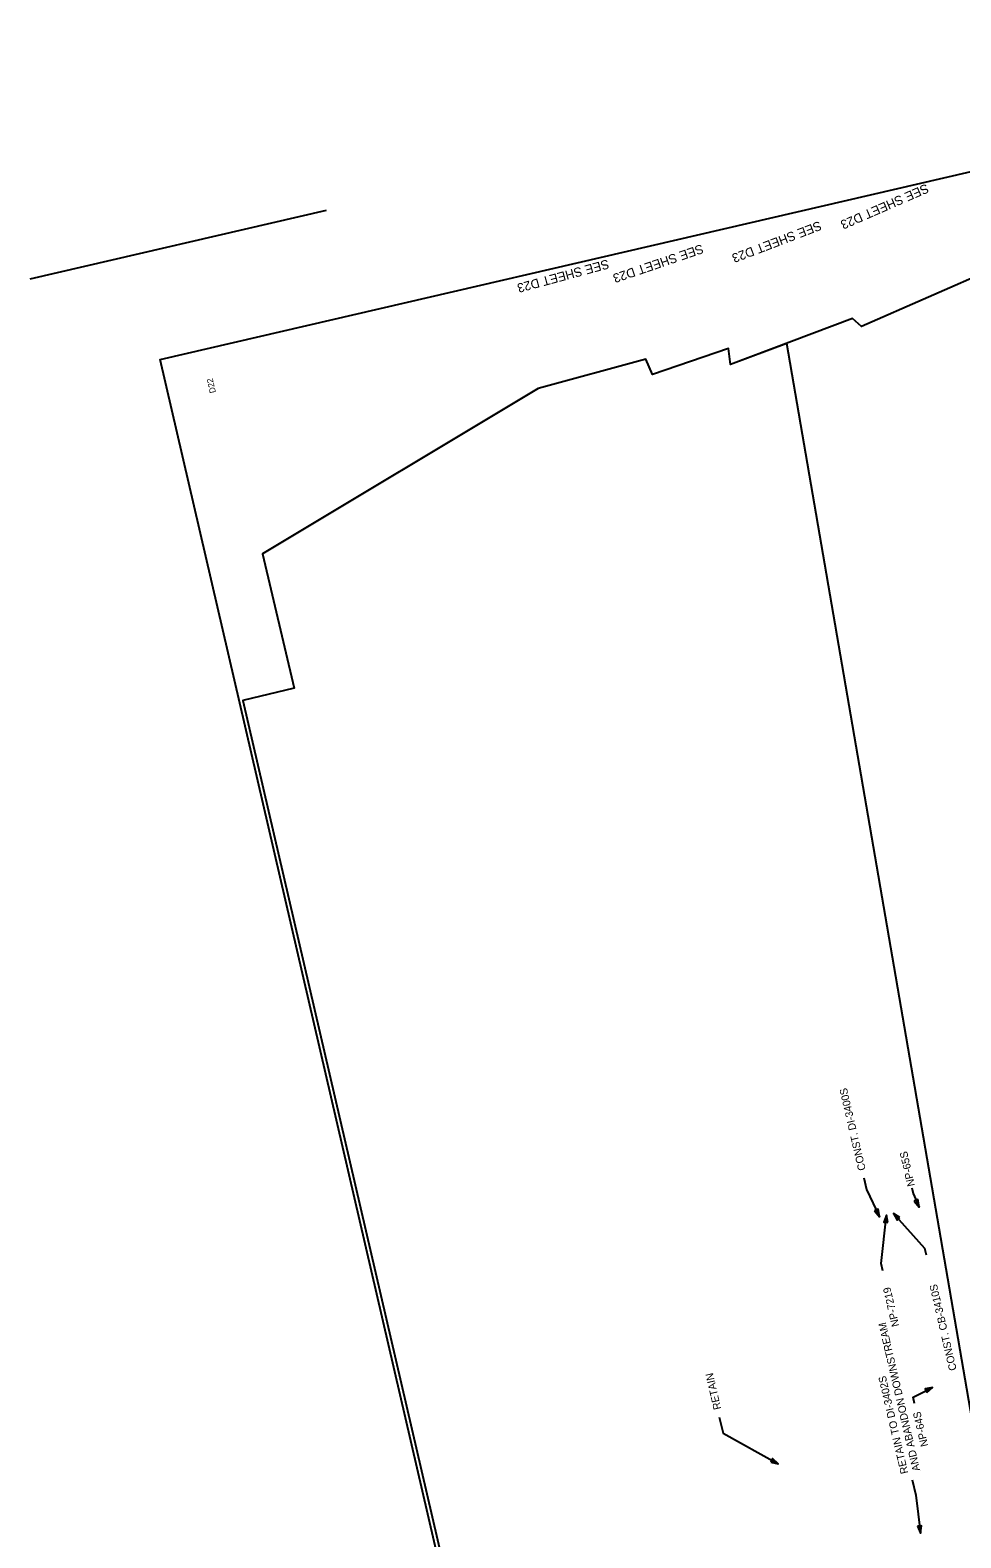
# Model space of a CAD drawing. Extents: x 1611522 to 1613146, y 1089913 to 1091760.
# Drawn here: x 1611522 to 1612133, y 1090772 to 1091760 of the extents above; entities that cross this region are included whole.
import ezdxf

# ---------------------------------------------------------------- set-up
doc = ezdxf.new("R2010")
doc.units = 0
for name, color, linetype in [('Level 2', 7, 'Continuous'), ('Plan_Clip', 7, 'Continuous'), ('RD_SHT_Bndy', 7, 'Continuous'), ('RD_SHT_MatchLine', 7, 'Continuous'), ('RD_TX_Drainage', 7, 'Continuous')]:
    doc.layers.add(name, color=color, linetype=linetype)

msp = doc.modelspace()

# ---------------------------------------------------------------- linework, layer by layer
at = {"layer": 'Level 2'}
msp.add_lwpolyline([(1611985.8, 1089912.73), (1611607.62, 1091544.48), (1612539.42, 1091760.44), (1612917.6, 1090128.69)], close=True, dxfattribs=at)
at = {"layer": 'Plan_Clip'}
msp.add_line((1611522.31, 1091597.29), (1611716.61, 1091642.32), dxfattribs=at)
msp.add_lwpolyline([(1612867.45, 1090326.93), (1612548.32, 1091705.46), (1612331.7, 1091644.99), (1612277.22, 1091632.37), (1612153.41, 1091561.04), (1612155.48, 1091604.44), (1612067.6, 1091566.09), (1612061.72, 1091571.33), (1611981.67, 1091541.05), (1611980.37, 1091551.71), (1611930.48, 1091534.68), (1611926.18, 1091544.55), (1611855.59, 1091525.38), (1611674.63, 1091416.97), (1611695.52, 1091328.83), (1611661.84, 1091320.85), (1611963.63, 1090019.87)], dxfattribs=at)
msp.add_lwpolyline([(1612867.45, 1090326.93), (1612548.32, 1091705.46), (1612331.7, 1091644.99), (1612277.22, 1091632.37), (1612153.41, 1091561.04), (1612155.48, 1091604.44), (1612067.6, 1091566.09), (1612061.72, 1091571.33), (1611981.67, 1091541.05), (1611980.37, 1091551.71), (1611930.48, 1091534.68), (1611926.18, 1091544.55), (1611855.59, 1091525.38), (1611674.63, 1091416.97), (1611695.52, 1091328.83), (1611661.84, 1091320.85), (1611963.63, 1090019.87)], dxfattribs=at)
msp.add_lwpolyline([(1612867.45, 1090326.93), (1612548.32, 1091705.46), (1612331.7, 1091644.99), (1612277.22, 1091632.37), (1612153.41, 1091561.04), (1612155.48, 1091604.44), (1612067.6, 1091566.09), (1612061.72, 1091571.33), (1611981.67, 1091541.05), (1611980.37, 1091551.71), (1611930.48, 1091534.68), (1611926.18, 1091544.55), (1611855.59, 1091525.38), (1611674.63, 1091416.97), (1611695.52, 1091328.83), (1611661.84, 1091320.85), (1611963.63, 1090019.87)], dxfattribs=at)
msp.add_lwpolyline([(1612867.45, 1090326.93), (1612548.32, 1091705.46), (1612331.7, 1091644.99), (1612277.22, 1091632.37), (1612153.41, 1091561.04), (1612155.48, 1091604.44), (1612067.6, 1091566.09), (1612061.72, 1091571.33), (1611981.67, 1091541.05), (1611980.37, 1091551.71), (1611930.48, 1091534.68), (1611926.18, 1091544.55), (1611855.59, 1091525.38), (1611674.63, 1091416.97), (1611695.52, 1091328.83), (1611661.84, 1091320.85), (1611963.63, 1090019.87)], dxfattribs=at)
msp.add_lwpolyline([(1612867.45, 1090326.93), (1612548.32, 1091705.46), (1612331.7, 1091644.99), (1612277.22, 1091632.37), (1612153.41, 1091561.04), (1612155.48, 1091604.44), (1612067.6, 1091566.09), (1612061.72, 1091571.33), (1611981.67, 1091541.05), (1611980.37, 1091551.71), (1611930.48, 1091534.68), (1611926.18, 1091544.55), (1611855.59, 1091525.38), (1611674.63, 1091416.97), (1611695.52, 1091328.83), (1611661.84, 1091320.85), (1611963.63, 1090019.87)], dxfattribs=at)
msp.add_lwpolyline([(1612867.45, 1090326.93), (1612548.32, 1091705.46), (1612331.7, 1091644.99), (1612277.22, 1091632.37), (1612153.41, 1091561.04), (1612155.48, 1091604.44), (1612067.6, 1091566.09), (1612061.72, 1091571.33), (1611981.67, 1091541.05), (1611980.37, 1091551.71), (1611930.48, 1091534.68), (1611926.18, 1091544.55), (1611855.59, 1091525.38), (1611674.63, 1091416.97), (1611695.52, 1091328.83), (1611661.84, 1091320.85), (1611963.63, 1090019.87)], dxfattribs=at)
msp.add_lwpolyline([(1612867.45, 1090326.93), (1612548.32, 1091705.46), (1612331.7, 1091644.99), (1612277.22, 1091632.37), (1612153.41, 1091561.04), (1612155.48, 1091604.44), (1612067.6, 1091566.09), (1612061.72, 1091571.33), (1611981.67, 1091541.05), (1611980.37, 1091551.71), (1611930.48, 1091534.68), (1611926.18, 1091544.55), (1611855.59, 1091525.38), (1611674.63, 1091416.97), (1611695.52, 1091328.83), (1611661.84, 1091320.85), (1611963.63, 1090019.87)], dxfattribs=at)
msp.add_lwpolyline([(1611963.63, 1090019.87), (1611998.55, 1090017.48), (1612099.34, 1090047.25), (1612244.44, 1090086.86), (1612241.08, 1090099.16), (1612268.58, 1090103.71), (1612018.61, 1091555.02), (1611981.67, 1091541.05), (1611980.37, 1091551.71), (1611930.48, 1091534.68), (1611926.18, 1091544.55), (1611855.59, 1091525.38), (1611674.63, 1091416.97), (1611695.52, 1091328.83), (1611661.84, 1091320.85)], close=True, dxfattribs=at)
at = {"layer": 'RD_TX_Drainage'}
for points in [[(1612069.18, 1091007.61), (1612070.93, 1091000.03), (1612079.44, 1090982.19)], [(1612100.55, 1091001.15), (1612101.42, 1090997.4), (1612105.45, 1090988.52)], [(1612081.54, 1090946.79), (1612080.47, 1090951.4), (1612084.07, 1090983.28)], [(1612110.17, 1090956.88), (1612109.15, 1090961.26), (1612088.69, 1090984.36)], [(1612102.5, 1090859.62), (1612101.5, 1090863.94), (1612114.24, 1090870.17)], [(1611974.33, 1090850.79), (1611976.79, 1090840.17), (1612012.93, 1090820.06)], [(1612100.91, 1090809.6), (1612103.25, 1090799.51), (1612106.34, 1090774.55)]]:
    msp.add_lwpolyline(points, dxfattribs=at)
for points in [[(1612102.28, 1090992.38), (1612105.45, 1090988.52), (1612104.63, 1090993.45)], [(1612076.2, 1090986), (1612079.44, 1090982.19), (1612078.53, 1090987.11)], [(1612084.81, 1090978.33), (1612084.07, 1090983.28), (1612082.24, 1090978.62)], [(1612092.86, 1090981.6), (1612088.69, 1090984.36), (1612090.93, 1090979.88)], [(1612110.47, 1090866.89), (1612114.24, 1090870.17), (1612109.33, 1090869.21)], [(1612008.08, 1090821.27), (1612012.93, 1090820.06), (1612009.34, 1090823.54)], [(1612104.46, 1090779.18), (1612106.34, 1090774.55), (1612107.03, 1090779.5)]]:
    msp.add_lwpolyline(points, close=True, dxfattribs=at)

# ---------------------------------------------------------------- texts
at = {"layer": 'RD_SHT_Bndy'}
msp.add_text('D22', height=4, rotation=103.04878, dxfattribs=at).set_placement((1611644.19, 1091522.86))
at = {"layer": 'RD_SHT_MatchLine'}
for rotation, p in [(203.58738, (1612110.09, 1091659.89)), (200.86202, (1612040, 1091635.38)), (198.84562, (1611962.71, 1091620.17)), (195.19668, (1611901.09, 1091610.14))]:
    msp.add_text('SEE SHEET D23', height=6, rotation=rotation, dxfattribs=at).set_placement(p)
at = {"layer": 'RD_TX_Drainage'}
for s, p in [('CONST. DI-3400S', (1612070.48, 1091013.05)), ('NP-65S', (1612102.76, 1091002.69)), ('NP-7219', (1612092.48, 1090910.65)), ('CONST. CB-3410S', (1612130.12, 1090881.85)), ('AND ABANDON DOWNSTREAM', (1612106.12, 1090815.93)), ('RETAIN', (1611975.64, 1090856.23)), ('RETAIN TO DI-3402S', (1612098.32, 1090814.13)), ('NP-64S', (1612111.47, 1090831.98))]:
    msp.add_text(s, height=5, rotation=103.04878, dxfattribs=at).set_placement(p)

doc.saveas('drawing.dxf')
